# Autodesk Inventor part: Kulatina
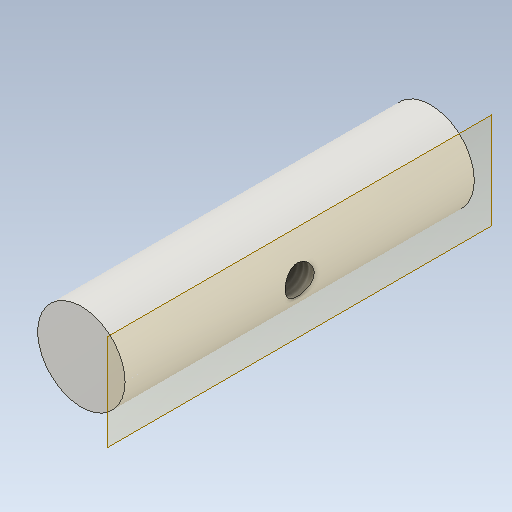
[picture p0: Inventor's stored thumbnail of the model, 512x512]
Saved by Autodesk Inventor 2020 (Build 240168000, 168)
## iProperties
Created: 2025-03
Part Number: Kulatina
Material: Ocel
Document SubType Name: Modeling
Designer: doma
Density: 7.85 g/cm^3
Appearance: Ocel
Mass: 191.922 g
Surface Area: 59.8992 cm^2
Volume: 24.4486 cm^3
Author: doma
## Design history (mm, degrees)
sketch "Náčrt1"
  geometry: C1 r 10 at (0, 0); 1 further point
  constraints: 1 centre point, 1 coincident
  dimensions: "d0" = 20 diameter of C1
extrude "Vysunutí1" new body sketch "Náčrt1" distance "d1" = 80; taper "d2" = 0 deg
node "Pracovní rovina1"
sketch "Náčrt2"
  geometry: L1 (-10, 0)-(-10, 80) reference; L2 (10, 0)-(10, 80) reference; L3 (10, 40)-(-10, 40); 2 further points
  constraints: 3 midpoint, 2 end point
hole "Díra1" sketch "Náčrt2" at (0, 40) diameter "d4" = 6.647; stored, may be unused: countersink angle "d8" = 90 deg, drill point angle "d10" = 118 deg; dims "d5" = 25, "d6" = 4, "d7" = 2, "d9" = 50
node "Těleso1"
